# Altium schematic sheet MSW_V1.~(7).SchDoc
size B; Organization: ORGANIZATION; Address1: ADDRESS 1; Address2: ADDRESS 2; Address3: ADDRESS 3; Address4: ADDRESS 4; Revision: -; SheetNumber: 1; SheetTotal: 1; ENG_APP_DATE: --/--/--; DSN_APP_DATE: --/--/--; CHK_APP_DATE: --/--/--
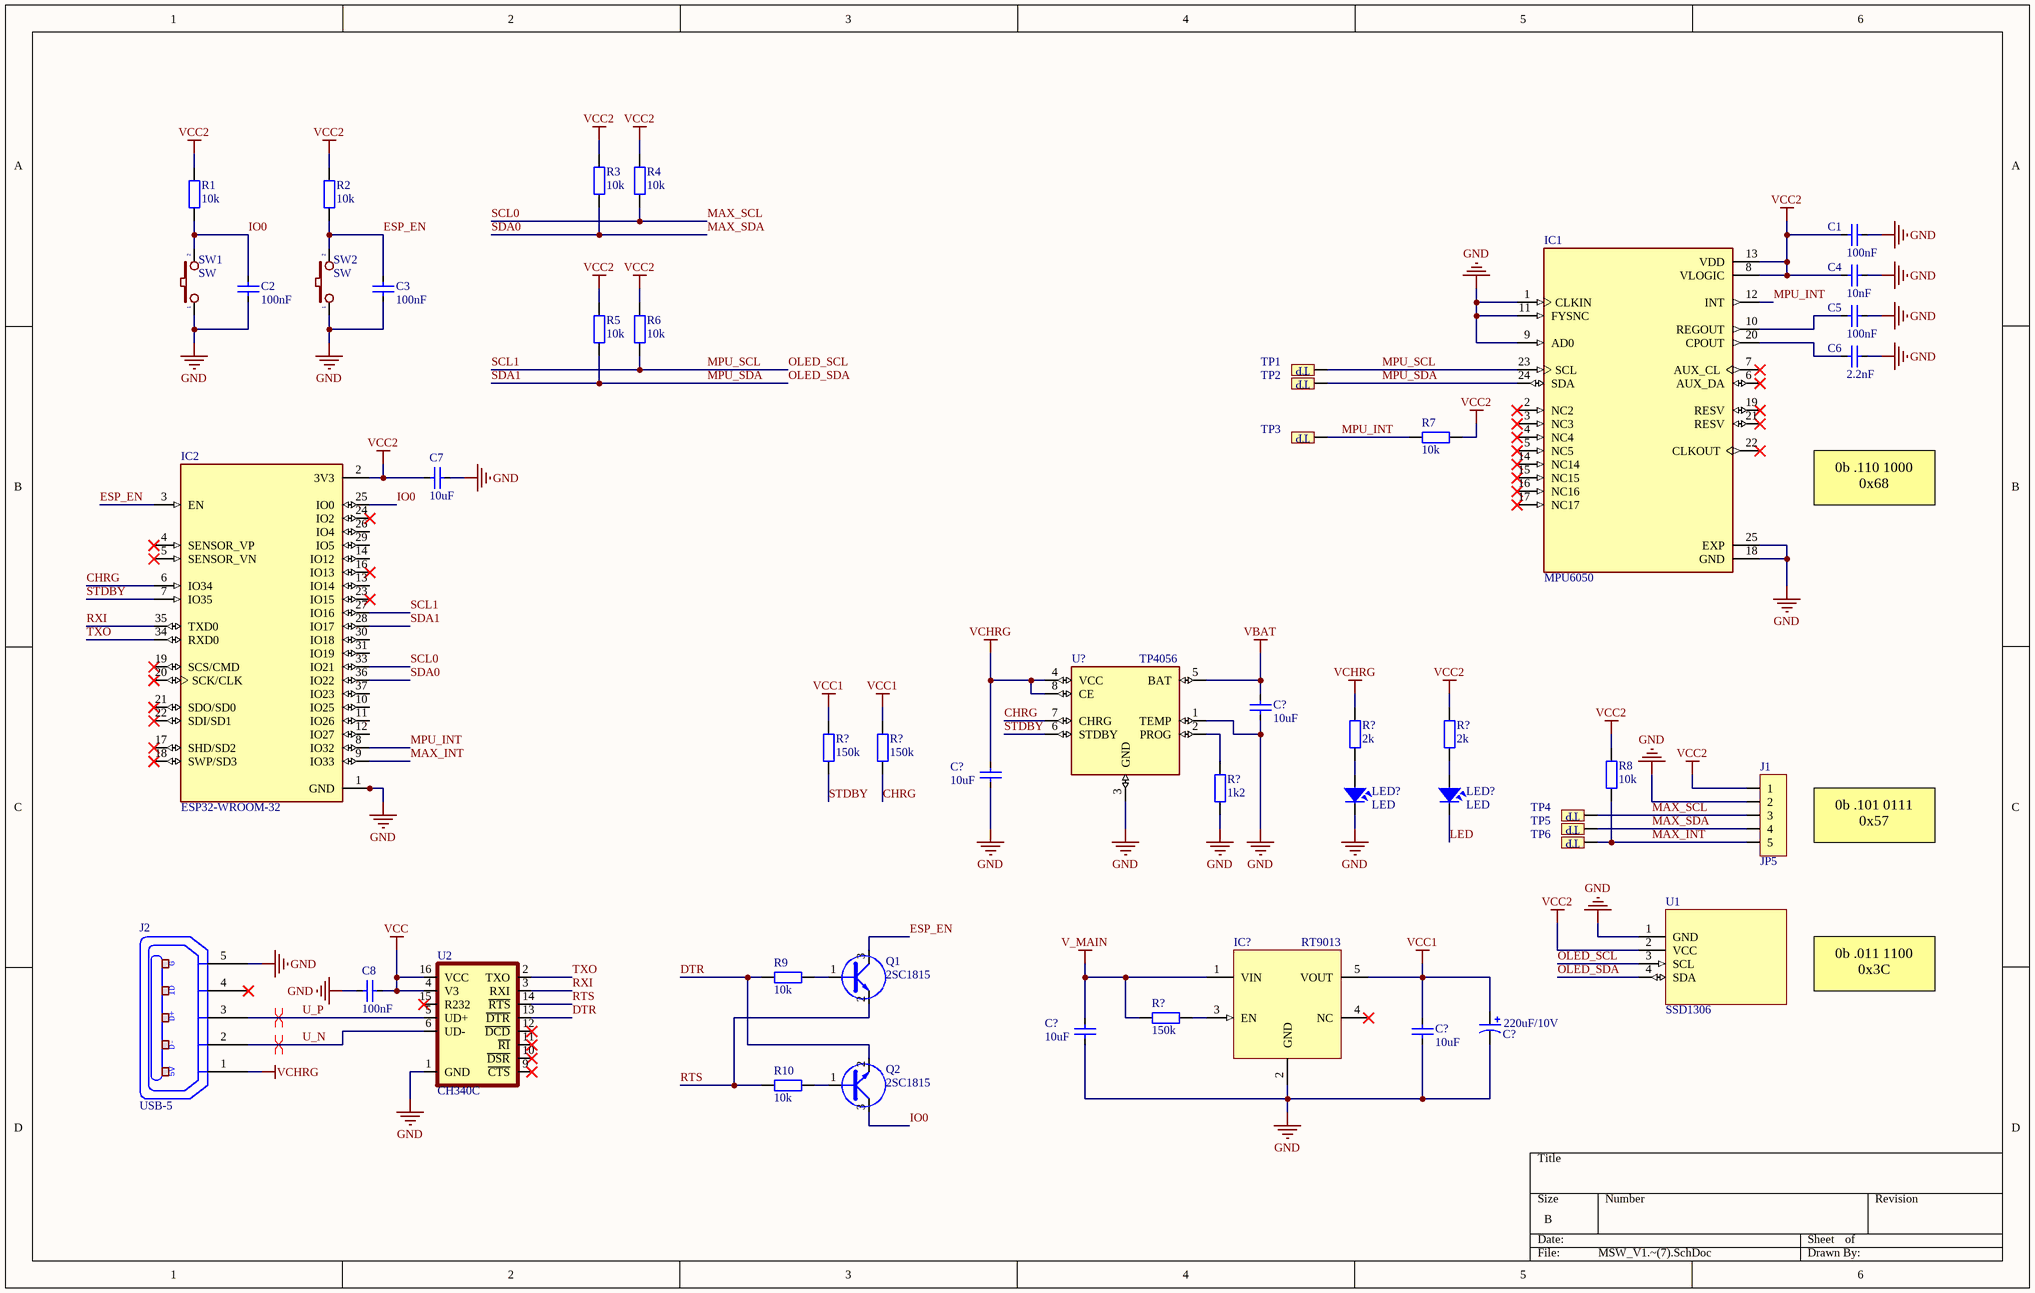
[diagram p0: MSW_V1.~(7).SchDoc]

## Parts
(Parts that share a designator on the sheet are numbered #1, #2 ... from top to bottom, then left to right.)
C1  100nF  [CAP_0603]
C2  100nF  [CAP_0603]
C3  100nF  [CAP_0603]
C4  10nF  [CAP_0603]
C5  100nF  [CAP_0603]
C6  2.2nF  [CAP_0603]
C7  10uF  [CAP_0603]
C8  100nF  [CAP_0603]
C?#1  10uF  [CAP_0603]
C?#2  10uF  [CAP_0603]
C?#3  220uF/10V  [CAP_7343]
C?#4  10uF  [CAP_0603]
C?#5  10uF  [CAP_0603]
IC1  MPU6050  [QFN24]
IC2  ESP32-WROOM-32  [MODULE_ESP32-WROOM-32]
IC?  RT9013  [SOT23-5]
J1  JP5  [Header5 - TH - 1.25MM]
J2  USB-5  [USB-M1]
LED?#1  LED  [LED-0805-Red]
LED?#2  LED  [LED-1206-Blue]
Q1  2SC1815  [SOT23D]
Q2  2SC1815  [SOT23D]
R1  10k  [RES-SMD-0603]
R2  10k  [RES-SMD-0603]
R3  10k  [RES-SMD-0603]
R4  10k  [RES-SMD-0603]
R5  10k  [RES-SMD-0603]
R6  10k  [RES-SMD-0603]
R7  10k  [RES-SMD-0603]
R8  10k  [RES-SMD-0603]
R9  10k  [RES-SMD-0603]
R10  10k  [RES-SMD-0603]
R?#1  2k  [RES-SMD-0603]
R?#2  2k  [RES-SMD-0603]
R?#3  150k  [RES-SMD-0603]
R?#4  150k  [RES-SMD-0603]
R?#5  1k2  [RES-SMD-0603]
R?#6  150k  [RES-SMD-0603]
SW1  SW  [SW 3x2x4]
SW2  SW  [SW 3x2x4]
TP1  TP  [TP_SMD]  (value not drawn)
TP2  TP  [TP_SMD]  (value not drawn)
TP3  TP  [TP_SMD]  (value not drawn)
TP4  TP  [TP_SMD]  (value not drawn)
TP5  TP  [TP_SMD]  (value not drawn)
TP6  TP  [TP_SMD]  (value not drawn)
U1  SSD1306  [OLED 1.3 SSD1306 PRETTY NON POLE]
U2  CH340C  [SOP-16]
U?  TP4056  [TP4056]

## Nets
GND: C1.1 C2.2 C3.2 C4.1 C5.1 C6.1 C7.2 C8.1 C?#1.1 C?#2.1 C?#3.2 C?#4.1 C?#5.1 IC1.1(CLKIN) IC1.9(AD0) IC1.11(FYSNC) IC1.18(GND) IC1.25(EXP) IC2.1(GND) IC2.15(GND) IC2.38(GND) IC2.39_1(GND) IC2.39_2(GND) IC2.39_3(GND) IC2.39_4(GND) IC2.39_5(GND) IC2.39_6(GND) IC2.39_7(GND) IC2.39_8(GND) IC2.39_9(GND) IC2.39_10(GND) IC2.39_11(GND) IC2.39_12(GND) IC2.39_13(GND) IC2.39_14(GND) IC2.39_15(GND) IC2.39_16(GND) IC2.39_17(GND) IC2.39_18(GND) IC2.39_19(GND) IC2.39_20(GND) IC2.39_21(GND) IC?.2(GND) J1.2 J2.5(P5) LED?#1.2 R?#5.1 SW1.1 SW2.1 U1.1(GND) U2.1(GND) U?.1(TEMP) U?.3(GND)
V_MAIN: C?#4.2 IC?.1(VIN) R?#6.1
VBAT: C?#1.2 U?.5(BAT)
VCC: C8.2 U2.4(V3) U2.16(VCC)
VCC1: C?#3.1 C?#5.2 IC?.5(VOUT) R?#3.1 R?#4.1
VCC2: C1.2 C4.2 C7.1 IC1.8(VLOGIC) IC1.13(VDD) IC2.2(3V3) J1.1 R1.2 R2.2 R3.2 R4.2 R5.2 R6.2 R7.1 R8.1 R?#2.2 U1.2(VCC)
VCHRG: C?#2.2 J2.1(P1) R?#1.2 U?.4(VCC) U?.8(CE)
CHRG: IC2.6(IO34) R?#4.2 U?.7(CHRG)
DTR: Q2.2(E) R9.2 U2.13(~{DTR})
ESP_EN: C3.1 IC2.3(EN) Q1.3(C) R2.1 SW2.2
IO0: C2.1 IC2.25(IO0) Q2.3(C) R1.1 SW1.2
LED: LED?#2.2
MAX_INT: IC2.9(IO33) J1.5 R8.2 TP6.1
MAX_SCL: IC2.33(IO21) J1.3 R4.1 TP4.1  [also labelled SCL0]
MAX_SDA: IC2.36(IO22) J1.4 R3.1 TP5.1  [also labelled SDA0]
MPU_INT: IC1.12(INT) IC2.8(IO32) R7.2 TP3.1
MPU_SCL: IC1.23(SCL) IC2.27(IO16) R6.1 TP1.1 U1.3(SCL)  [also labelled OLED_SCL, SCL1]
MPU_SDA: IC1.24(SDA) IC2.28(IO17) R5.1 TP2.1 U1.4(SDA)  [also labelled OLED_SDA, SDA1]
RTS: Q1.2(E) R10.2 U2.14(~{RTS})
RXI: IC2.35(TXD0) U2.3(RXI)
STDBY: IC2.7(IO35) R?#3.2 U?.6(STDBY)
TXO: IC2.34(RXD0) U2.2(TXO)
U_N: J2.2(P2) U2.6(UD-)
U_P: J2.3(P3) U2.5(UD+)
NetC5_2: C5.2 IC1.10(REGOUT)
NetC6_2: C6.2 IC1.20(CPOUT)
NetIC?_3: IC?.3(EN) R?#6.2
NetLED?#1_1: LED?#1.1 R?#1.1
NetLED?#2_1: LED?#2.1 R?#2.1
NetQ1_1: Q1.1(B) R9.1
NetQ2_1: Q2.1(B) R10.1
NetR?#5_2: R?#5.2 U?.2(PROG)

Not connected (* = marked no-connect by the designer): IC1 2(NC2)* 3(NC3)* 4(NC4)* 5(NC5)* 6(AUX_DA)* 7(AUX_CL)* 14(NC14)* 15(NC15)* 16(NC16)* 17(NC17)* 19(RESV)* 21(RESV)* 22(CLKOUT)*; IC2 4(SENSOR_VP)* 5(SENSOR_VN)* 10(IO25) 11(IO26) 12(IO27) 13(IO14) 14(IO12) 16(IO13)* 17(SHD/SD2)* 18(SWP/SD3)* 19(SCS/CMD)* 20(SCK/CLK)* 21(SDO/SD0)* 22(SDI/SD1)* 23(IO15)* 24(IO2)* 26(IO4) 29(IO5) 30(IO18) 31(IO19) 37(IO23); IC? 4(NC)*; J2 4(P4)*; U2 9(~{CTS})* 10(~{DSR})* 11(~{RI})* 12(~{DCD})* 15(R232)*

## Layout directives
differential pair: U_N, U_P

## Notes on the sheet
- 0b .110 1000
  0x68
- 0b .101 0111
  0x57
- 0b .011 1100
  0x3C

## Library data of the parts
C1-C8 C?#1 C?#2 C?#4 C?#5 = CapSMD: Capacitor; Value: 33p
C?#3 = CAP_TAN_SMD: Polazied Tantalum Capacitor
IC1 = MPU6050_Chip: 3-axis gyroscope, 3-axis accelerometer
IC2 = ESP32-WROOM-32: Bluetooth, WiFi Transceiver Module 2.4GHz ~ 2.5GHz Surface Mount; MF: Espressif Systems
IC? = RT9013: RT9013-33GB IC REG LINEAR 3.3V 500mA SOT23-5
J1 = JP5x1: WR-PHD 2.54 mm Angled Socket Header; Manufacturer: W¨¹rth Elektronik eiSos GmbH; partNo: 613005143121; ComponentLink1 Description: Manufacturer; ComponentLink2 Description: Datasheet; NoPins: 05
J2 = USB-5: Manufacturer: FCI; Manufacturer Part Number: 10118193-0001LF; Connector Type: USB - micro B; Number of Contacts: 5; Gender: Receptacle; Specifications: USB 2.0; .Creator: MM; .Checked PCB: RF
LED?#1 LED?#2 = LED: LED Single colour Green and Red; Value: LED 3 ly Single Colour
Q1 Q2 = C1815: NPN 600mW, ECB; Value: C1815
R1-R10 R?#1-R?#6 = Resistor - SMD: Resistor SMD; Manufacturer: Generic Components; Class: Passive
SW1 SW2 = SW2: Switch button 2 pin; Value: SW chip 2 pin
TP1-TP6 = TP: CONNECT 1
U1 = OLED 1.3 SSD1306: OLED Display 1.3" SSD1306
U2 = CH340C: USB to serial chip CH340; MF: WCH
U? = TP4056: Complete single cell Li-Ion battery with a constant current / constant voltage linear charger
